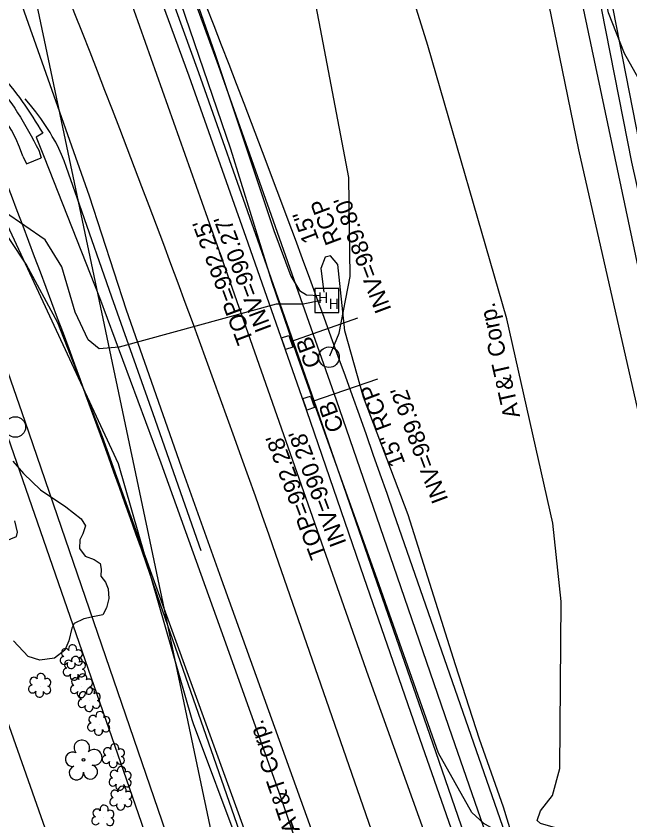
# Model space of a CAD drawing. Extents: x 1614427 to 1617186, y 896524 to 905462.
# Drawn here: x 1616176 to 1616323.1, y 903837.6 to 904030.2 of the extents above; entities that cross this region are included whole.
import ezdxf

# ---------------------------------------------------------------- set-up
doc = ezdxf.new("R2010")
doc.units = 0
for name, color, linetype in [('Exist Horizontal Alignment', 7, 'Continuous'), ('Exist Other Culture Fence Line', 7, 'Continuous'), ('Exist Right of Way Line', 7, 'Continuous'), ('Exist Roads Curbs', 7, 'Continuous'), ('Exist Roads EOP', 7, 'Continuous'), ('Exist Roads EOP Other', 7, 'Continuous'), ('Exist Roads EOT', 7, 'Continuous'), ('Exist Structure Minor Catch Basin', 7, 'Continuous'), ('Exist Structure Minor Catch Basin Text', 7, 'Continuous'), ('Exist Structure Minor Catch Basin Top Elevation', 7, 'Continuous'), ('Exist Structure Minor Pipes RCP 15 Inch', 7, 'Continuous'), ('Exist Structure Minor Pipes RCP 15 Inch Invert', 7, 'Continuous'), ('Exist Structure Minor Pipes RCP 15 Inch Text', 7, 'Continuous'), ('Exist Utilities Gas UG Line SUE LOS B', 7, 'Continuous'), ('Exist Utilities Other Pole CELL', 7, 'Continuous'), ('Exist Utilities Power UG Cable SUE LOS B', 7, 'Continuous'), ('Exist Utilities Power UG Cable SUE LOS D', 7, 'Continuous'), ('Exist Utilities Telephone Hand Hole CELL', 7, 'Continuous'), ('Exist Utilities Telephone UG Cable SUE LOS B', 7, 'Continuous'), ('Exist Utilities Telephone UG Cable SUE LOS B Text', 7, 'Continuous'), ('Exist Utilities Telephone UG FO SUE LOS B', 7, 'Continuous'), ('Exist Utilities Telephone UG FO SUE LOS B Text', 7, 'Continuous'), ('Exist Utilities Telephone UG FO SUE LOS D', 7, 'Continuous'), ('Exist Utilities TV UG Cable SUE LOS D', 7, 'Continuous'), ('Exist Utilities TV UG FO Cable SUE LOS D', 7, 'Continuous'), ('Exist Utilities Water UG Line SUE LOS B', 7, 'Continuous'), ('Exist Vegetation Hedge Row', 7, 'Continuous'), ('Exist Vegetation Shrub CELL', 7, 'Continuous'), ('Exist Vegetation Tree CELL', 7, 'Continuous'), ('Exist Vegetation Woods Line', 7, 'Continuous')]:
    doc.layers.add(name, color=color, linetype=linetype)

msp = doc.modelspace()

# ---------------------------------------------------------------- linework, layer by layer
at = {"layer": 'Exist Horizontal Alignment'}
msp.add_line((1616576.74, 902927.89), (1616238.24, 903901.21), dxfattribs=at)
msp.add_arc((1612992.37, 902768.76), 3437.75, 19.23333, 21.86667, dxfattribs=at)
at = {"layer": 'Exist Other Culture Fence Line'}
msp.add_lwpolyline([(1616211.35, 903767.58), (1616195.22, 903813.36), (1616186.56, 903825.42), (1616168.75, 903875.81), (1616153.63, 903916.5), (1616129.58, 903932.3), (1616098.05, 903952.43), (1616082.04, 903962.19), (1616045.01, 903949.52), (1616000.86, 903933.41), (1615934.86, 903910.4), (1615905.89, 903899.71)], dxfattribs=at)
at = {"layer": 'Exist Right of Way Line'}
for p, q in [((1616010.65, 905462.23), (1616993.32, 900797.76)), ((1615887.44, 905426.15), (1616864.55, 900788.06)), ((1616548.32, 902918.27), (1616209.91, 903891.34))]:
    msp.add_line(p, q, dxfattribs=at)
msp.add_lwpolyline([(1616348.8, 903674.62), (1616266.57, 903911.08), (1616266.56, 903911.09)], dxfattribs=at)
for radius, start, end in [(3467.75, 19.23333, 21.86667), (3407.75, 19.23358, 21.34613)]:
    msp.add_arc((1612992.37, 902768.76), radius, start, end, dxfattribs=at)
at = {"layer": 'Exist Roads Curbs'}
msp.add_line((1616181.42, 903998.08), (1616182.01, 903996.25), dxfattribs=at)
msp.add_lwpolyline([(1616117.86, 904294.32), (1616132.6, 904254.66), (1616147.03, 904215.59), (1616161.55, 904176.09), (1616175.82, 904137.25), (1616190.47, 904097.09), (1616204.98, 904057.33), (1616219.73, 904016.73), (1616233.88, 903976.63), (1616247.93, 903936.53), (1616261.75, 903896.6), (1616275.82, 903856.12), (1616289.5, 903816.57), (1616303.58, 903775.98), (1616318, 903734.48)], dxfattribs=at)
msp.add_spline([(1616134.69, 904023.46), (1616139.29, 904024.31), (1616146.51, 904024.55), (1616150.66, 904023.89), (1616157.04, 904022.42), (1616170, 904014.96), (1616181.42, 903998.08)], degree=3, dxfattribs=at)
at = {"layer": 'Exist Roads EOP'}
for points in [[(1616115.61, 904293.45), (1616130.22, 904253.88), (1616144.71, 904214.78), (1616159.36, 904175.17), (1616173.54, 904136.33), (1616188.19, 904096.22), (1616202.56, 904056.51), (1616217.36, 904015.9), (1616231.52, 903975.89), (1616245.62, 903935.7), (1616259.38, 903895.73), (1616273.35, 903855.36), (1616287.12, 903815.79), (1616301.21, 903775.08), (1616315.66, 903733.58)], [(1616115.61, 904293.45), (1616130.22, 904253.88), (1616144.71, 904214.78), (1616159.36, 904175.17), (1616173.54, 904136.33), (1616188.19, 904096.22), (1616202.56, 904056.51), (1616217.36, 904015.9), (1616231.52, 903975.89), (1616245.62, 903935.7), (1616259.38, 903895.73), (1616273.35, 903855.36), (1616287.12, 903815.79)], [(1616182.37, 904002.15), (1616180.78, 904001.18), (1616182.71, 903996.46), (1616196.01, 903962.82), (1616210.69, 903923.18), (1616225.09, 903883.2), (1616239.3, 903843.39), (1616253.05, 903803.36), (1616266.79, 903762.41), (1616281.33, 903720.95)]]:
    msp.add_lwpolyline(points, dxfattribs=at)
msp.add_spline([(1616134.32, 904025.99), (1616139, 904026.81), (1616146.76, 904026.96), (1616150.97, 904026.42), (1616157.68, 904024.84), (1616171.63, 904016.64), (1616182.37, 904002.15)], degree=3, dxfattribs=at)
at = {"layer": 'Exist Roads EOP Other'}
for points in [[(1616122.43, 904296.46), (1616137.34, 904256.3), (1616151.63, 904217.58), (1616166.45, 904177.4), (1616180.52, 904139.04), (1616195.16, 904098.73), (1616209.58, 904059.11), (1616224.45, 904018.46), (1616238.58, 903978.47), (1616252.68, 903938.24), (1616266.45, 903898.41), (1616280.47, 903857.78), (1616294.14, 903818.38), (1616308.3, 903777.63), (1616322.66, 903736.35)], [(1616177.61, 903996.7), (1616178.44, 903994.84), (1616181.96, 903996.23)]]:
    msp.add_lwpolyline(points, dxfattribs=at)
msp.add_ellipse((1616144.89, 903985.92), major_axis=(8.54, 33.37), ratio=0.999906, start_param=5.280969, end_param=6.32168, dxfattribs=at)
at = {"layer": 'Exist Roads EOT'}
msp.add_lwpolyline([(1616220.38, 903902.1), (1616208.82, 903934.88), (1616198.96, 903962.91), (1616191.16, 903985.11), (1616188.04, 903993.96), (1616187.51, 903995.51), (1616186.9, 903997.04), (1616186.23, 903998.53), (1616185.48, 903999.99), (1616184.66, 904001.41), (1616184.11, 904002.3), (1616183.05, 904004.02), (1616181.92, 904005.69), (1616180.72, 904007.32), (1616179.46, 904008.9), (1616178.14, 904010.43), (1616178.13, 904010.44)], dxfattribs=at)
at = {"layer": 'Exist Structure Minor Catch Basin'}
for points in [[(1616242.34, 903950.91), (1616240.54, 903950.31), (1616239.57, 903953.15), (1616241.39, 903953.73), (1616242.34, 903950.91)], [(1616247.49, 903936.4), (1616245.71, 903935.79), (1616244.74, 903938.57), (1616246.55, 903939.19), (1616247.49, 903936.4)]]:
    msp.add_lwpolyline(points, dxfattribs=at)
at = {"layer": 'Exist Structure Minor Pipes RCP 15 Inch'}
for p, q in [((1616241.86, 903952.26), (1616257.87, 903957.95)), ((1616241.86, 903952.26), (1616257.87, 903957.95)), ((1616262.61, 903943.26), (1616247.04, 903937.86)), ((1616262.61, 903943.26), (1616247.04, 903937.86))]:
    msp.add_line(p, q, dxfattribs=at)
at = {"layer": 'Exist Utilities Gas UG Line SUE LOS B'}
msp.add_lwpolyline([(1616229.48, 903831.39), (1616218.51, 903860.65), (1616218.15, 903861.58), (1616200.49, 903922.94), (1616158.51, 904013.15), (1616156.79, 904018.63), (1616125.02, 904117.19), (1616112.76, 904150.51)], dxfattribs=at)
at = {"layer": 'Exist Utilities Other Pole CELL'}
for centre in [(1616250.99, 903948.48), (1616175.8, 903931.77)]:
    msp.add_circle(centre, 2.46, dxfattribs=at)
at = {"layer": 'Exist Utilities Power UG Cable SUE LOS B'}
msp.add_lwpolyline([(1616251.18, 903948.78), (1616253.44, 903954.26), (1616256.05, 903967.83), (1616255.72, 903991.57), (1616246.33, 904041.11), (1616238.14, 904073.94), (1616217.33, 904136.89), (1616206.18, 904181.46), (1616196.65, 904215.76), (1616195.81, 904229.77), (1616189.23, 904257.04), (1616182.09, 904267.79), (1616161.47, 904291.96), (1616139.96, 904327.82), (1616127.72, 904364.11), (1616117.11, 904392.88), (1616109.92, 904408.61)], dxfattribs=at)
at = {"layer": 'Exist Utilities Power UG Cable SUE LOS D'}
msp.add_lwpolyline([(1616236.67, 903748.63), (1616173.38, 903931.36), (1616078.95, 904203.95), (1616024.11, 904362.27)], dxfattribs=at)
at = {"layer": 'Exist Utilities Telephone Hand Hole CELL'}
for p, q in [((1616247.59, 903964.96), (1616247.59, 903959.24)), ((1616253.32, 903964.96), (1616247.59, 903964.96)), ((1616253.32, 903959.24), (1616253.32, 903964.96)), ((1616250.46, 903962.1), (1616250.46, 903962.1)), ((1616247.59, 903959.24), (1616253.32, 903959.24))]:
    msp.add_line(p, q, dxfattribs=at)
at = {"layer": 'Exist Utilities Telephone UG Cable SUE LOS B'}
msp.add_lwpolyline([(1616264.73, 903785.56), (1616225.23, 903895.34), (1616215.6, 903922.1), (1616202.44, 903959.77), (1616193.59, 903987.06), (1616171.78, 904048.65), (1616147.44, 904117.95), (1616126.43, 904148.49), (1616103.05, 904238.24), (1616092.8, 904266.31), (1616073.76, 904321.1), (1616067.14, 904333.96), (1616066.19, 904334.49), (1616064.27, 904334.96), (1616057.18, 904332.89), (1616048.96, 904331.57)], dxfattribs=at)
at = {"layer": 'Exist Utilities Telephone UG FO SUE LOS B'}
for points in [[(1616305.86, 903835.58), (1616301.71, 903836.75), (1616300.93, 903837.51), (1616301.7, 903839.81), (1616304.58, 903843.5), (1616306.34, 903849.92), (1616306.68, 903889.95), (1616304.63, 903908.72), (1616293.63, 903957.65), (1616274.72, 904023.16), (1616260.11, 904069.82), (1616245.31, 904104.27), (1616231.41, 904145.88), (1616215.41, 904195.22), (1616204.68, 904240.22), (1616199.33, 904261.21), (1616183.55, 904304.43), (1616162.6, 904355.73), (1616148.58, 904401.99), (1616136.38, 904433.35), (1616120.49, 904476.41), (1616105.61, 904520.44), (1616089.41, 904571.33)], [(1616227.47, 903998.34), (1616211.12, 904046.11), (1616197.17, 904083.61), (1616180.84, 904129.23), (1616169.23, 904161.39), (1616162.49, 904178.57), (1616139.6, 904240.02), (1616090.77, 904372.44), (1616071.57, 904435.61), (1616056.71, 904499.76), (1616046.9, 904559.71)], [(1616174.04, 904166.31), (1616172.79, 904159.75), (1616179.29, 904147.79), (1616189.78, 904114.21), (1616200.72, 904084.94), (1616209.79, 904060.82), (1616223.62, 904021.24), (1616237.73, 903978.87), (1616241.81, 903967.87), (1616243.9, 903964.46), (1616245.56, 903963.47), (1616248.71, 903963.24)], [(1616249.11, 903962.1), (1616244.79, 903961.17), (1616238.35, 903961.16), (1616200.69, 903950.89), (1616195.93, 903950.49), (1616193.23, 903952.67), (1616190.15, 903959.25), (1616186.96, 903970.12), (1616182.94, 903976.59), (1616168.24, 903986.65), (1616161.85, 903994.6), (1616153.95, 904004.6), (1616148.06, 904010.09), (1616140.82, 904013.46), (1616124.88, 904014.78), (1616105.51, 904016.53), (1616064.53, 904012.24), (1616026.51, 904012.8), (1615984.81, 904011.98), (1615950.8, 904014.23), (1615922.36, 904016.58), (1615897.75, 904017.11), (1615884.16, 904015.33), (1615877.39, 904015.58)], [(1616231.95, 903831.99), (1616208.49, 903896.38), (1616196.66, 903929.39), (1616185.98, 903956.69), (1616178.38, 903970.82), (1616170.63, 903982.39), (1616159.03, 903993.51), (1616152.27, 904000.63), (1616146.16, 904003.93), (1616135.11, 904008.46), (1616113.93, 904008.67), (1616072.1, 904003.93), (1616027.82, 904003.5), (1615985.23, 904002.2), (1615950.55, 904003.04), (1615906.43, 904005.88), (1615898.01, 904002.34)], [(1616305.43, 903834.95), (1616296.33, 903833.77), (1616291.87, 903834.62), (1616288.13, 903836.73), (1616285.25, 903839.39), (1616277.28, 903853.64), (1616262.51, 903895.33), (1616243.28, 903949.17), (1616237.33, 903966.37), (1616227.47, 903998.34)], [(1616287.08, 903856.98), (1616281.28, 903874.75), (1616269.99, 903910.7), (1616259.25, 903938.88), (1616254.76, 903954.77), (1616253.07, 903970.72), (1616251.35, 903972.79), (1616250.05, 903972.47), (1616249.02, 903969.73), (1616249.73, 903964.06)], [(1616301.65, 903812.03), (1616292.8, 903840.69), (1616287.08, 903856.98)]]:
    msp.add_lwpolyline(points, dxfattribs=at)
at = {"layer": 'Exist Utilities Telephone UG FO SUE LOS D'}
msp.add_lwpolyline([(1616412.38, 903583.74), (1616374.62, 903777.9), (1616326.11, 903996.08), (1616269.81, 904283.52), (1616224.71, 904447.92), (1616220.83, 904470.3)], dxfattribs=at)
at = {"layer": 'Exist Utilities TV UG Cable SUE LOS D'}
msp.add_lwpolyline([(1616295.86, 903492.41), (1616273.81, 903595.89), (1616240.99, 903749.89), (1616178.16, 903933.06), (1616083.67, 904205.09), (1616028.66, 904363.47)], dxfattribs=at)
at = {"layer": 'Exist Utilities TV UG FO Cable SUE LOS D'}
msp.add_lwpolyline([(1616615.13, 902920.57), (1616559.6, 903084.29), (1616508.29, 903236.97), (1616433.95, 903449.2), (1616409.28, 903583.28), (1616372.35, 903777.82), (1616323.57, 903995.2), (1616266.96, 904282.87), (1616220.39, 904446.95), (1616216.24, 904469.3), (1616198.7, 904563.75), (1616189.79, 904725.95), (1616160.9, 904944.94), (1616137.72, 905120.69)], dxfattribs=at)
at = {"layer": 'Exist Utilities Water UG Line SUE LOS B'}
msp.add_lwpolyline([(1616526.94, 903118.95), (1616504.59, 903181.23), (1616480.02, 903252.46), (1616446.17, 903345), (1616411.28, 903445.17), (1616385.62, 903515.15), (1616350.02, 903616.87), (1616323.73, 903691.37), (1616291.21, 903786.26), (1616260.45, 903872.07), (1616224.66, 903974.02), (1616192.08, 904066.13), (1616173.94, 904118.11), (1616130.42, 904237.78), (1616097.26, 904331.65), (1616083.48, 904374.45), (1616069.85, 904420.53), (1616059.14, 904458.49), (1616050.85, 904496.39), (1616045.84, 904527.76), (1616030.28, 904669.9)], dxfattribs=at)
at = {"layer": 'Exist Vegetation Hedge Row'}
for points in [[(1616358.61, 903855.18), (1616347.94, 903857.23), (1616338.59, 903879.82), (1616325.43, 903934.2), (1616310.92, 903998.19), (1616300.46, 904048.92), (1616299.41, 904076.85), (1616293.79, 904094.09), (1616289.23, 904099.45), (1616283.51, 904102.81), (1616273.57, 904103.44), (1616270.33, 904105.91), (1616268.99, 904109.41), (1616269.89, 904113.78), (1616274.57, 904118.52), (1616280.14, 904127.79), (1616280.93, 904138.82), (1616278.97, 904162.54), (1616274.72, 904185.17), (1616262.08, 904240.76), (1616253.29, 904278.87)], [(1616175.22, 903923.56), (1616177.74, 903920.65), (1616181.81, 903916.73), (1616187.91, 903912.61), (1616191.57, 903909.72), (1616192.58, 903908.06), (1616191.97, 903906.19), (1616191.26, 903904.72), (1616191.19, 903902.61), (1616192.51, 903900.8), (1616194.66, 903900.03), (1616196.17, 903899.02), (1616196.34, 903897.7), (1616196.32, 903896.05), (1616197.4, 903894.56), (1616198.07, 903892.95), (1616198.2, 903890.7), (1616197.62, 903888.47), (1616196.77, 903886.75), (1616194.75, 903886.38), (1616192.22, 903885.82), (1616189.91, 903884.65), (1616189.34, 903883.59), (1616188.66, 903880.49), (1616187.64, 903878.32), (1616185.16, 903876.37), (1616181.69, 903875.89), (1616178.86, 903876.75), (1616175.33, 903880.56)], [(1616173.36, 903904.42), (1616176.09, 903905.55), (1616176.32, 903906.53), (1616175.65, 903909.29)]]:
    msp.add_lwpolyline(points, dxfattribs=at)
at = {"layer": 'Exist Vegetation Shrub CELL'}
for p, q in [((1616189.3, 903876.55), (1616189.3, 903876.55)), ((1616190.01, 903873.77), (1616190.01, 903873.77)), ((1616181.72, 903869.69), (1616181.72, 903869.69)), ((1616191.74, 903869.57), (1616191.74, 903869.57)), ((1616193.58, 903866.24), (1616193.58, 903866.24)), ((1616195.87, 903860.56), (1616195.87, 903860.56)), ((1616199.37, 903852.83), (1616199.37, 903852.83)), ((1616201, 903847.4), (1616201, 903847.4)), ((1616201.17, 903842.64), (1616201.17, 903842.64)), ((1616196.86, 903838.12), (1616196.86, 903838.12))]:
    msp.add_line(p, q, dxfattribs=at)
for centre, radius, start, end in [((1616189.53, 903878.59), 0.99, 334.8391, 200.4717), ((1616187.81, 903877.68), 0.968, 35.8908, 245.4216), ((1616190.97, 903877.42), 0.929, 284.4567, 126.0861), ((1616187.5, 903875.84), 0.955, 95.1099, 327.9534), ((1616188.53, 903874.89), 0.968, 35.8908, 245.4216), ((1616190.24, 903875.81), 0.99, 334.8391, 200.4717), ((1616190.93, 903875.62), 0.937, 204.9913, 73.4601), ((1616191.68, 903874.64), 0.929, 284.4567, 126.0861), ((1616188.21, 903873.06), 0.955, 95.1099, 327.9534), ((1616189.17, 903874.86), 0.984, 151.2797, 21.387), ((1616191.65, 903872.84), 0.937, 204.9913, 73.4601), ((1616180.24, 903870.82), 0.968, 35.8908, 245.4216), ((1616181.95, 903871.73), 0.99, 334.8391, 200.4717), ((1616189.88, 903872.08), 0.984, 151.2797, 21.387), ((1616191.97, 903871.61), 0.99, 334.8391, 200.4717), ((1616179.92, 903868.99), 0.955, 95.1099, 327.9534), ((1616183.4, 903870.56), 0.929, 284.4567, 126.0861), ((1616189.94, 903868.87), 0.955, 95.1099, 327.9534), ((1616190.26, 903870.7), 0.968, 35.8908, 245.4216), ((1616193.41, 903870.44), 0.929, 284.4567, 126.0861), ((1616181.6, 903868.01), 0.984, 151.2797, 21.387), ((1616183.36, 903868.76), 0.937, 204.9913, 73.4601), ((1616191.61, 903867.89), 0.984, 151.2797, 21.387), ((1616192.1, 903867.36), 0.968, 35.8908, 245.4216), ((1616193.38, 903868.64), 0.937, 204.9913, 73.4601), ((1616193.81, 903868.28), 0.99, 334.8391, 200.4717), ((1616195.25, 903867.11), 0.929, 284.4567, 126.0861), ((1616191.78, 903865.53), 0.955, 95.1099, 327.9534), ((1616195.22, 903865.31), 0.937, 204.9913, 73.4601), ((1616193.45, 903864.55), 0.984, 151.2797, 21.387), ((1616194.39, 903861.69), 0.968, 35.8908, 245.4216), ((1616196.1, 903862.6), 0.99, 334.8391, 200.4717), ((1616197.54, 903861.43), 0.929, 284.4567, 126.0861), ((1616194.07, 903859.86), 0.955, 95.1099, 327.9534), ((1616197.51, 903859.63), 0.937, 204.9913, 73.4601), ((1616195.74, 903858.88), 0.984, 151.2797, 21.387), ((1616197.89, 903853.95), 0.968, 35.8908, 245.4216), ((1616199.6, 903854.87), 0.99, 334.8391, 200.4717), ((1616201.04, 903853.69), 0.929, 284.4567, 126.0861), ((1616197.57, 903852.12), 0.955, 95.1099, 327.9534), ((1616201.01, 903851.9), 0.937, 204.9913, 73.4601), ((1616199.24, 903851.14), 0.984, 151.2797, 21.387), ((1616199.51, 903848.53), 0.968, 35.8908, 245.4216), ((1616201.23, 903849.44), 0.99, 334.8391, 200.4717), ((1616202.67, 903848.27), 0.929, 284.4567, 126.0861), ((1616199.2, 903846.69), 0.955, 95.1099, 327.9534), ((1616202.63, 903846.47), 0.937, 204.9913, 73.4601), ((1616199.68, 903843.77), 0.968, 35.8908, 245.4216), ((1616200.87, 903845.71), 0.984, 151.2797, 21.387), ((1616201.39, 903844.68), 0.99, 334.8391, 200.4717), ((1616199.37, 903841.93), 0.955, 95.1099, 327.9534), ((1616202.84, 903843.51), 0.929, 284.4567, 126.0861), ((1616197.09, 903840.16), 0.99, 334.8391, 200.4717), ((1616201.04, 903840.96), 0.984, 151.2797, 21.387), ((1616202.8, 903841.71), 0.937, 204.9913, 73.4601), ((1616195.38, 903839.25), 0.968, 35.8908, 245.4216), ((1616198.53, 903838.99), 0.929, 284.4567, 126.0861), ((1616195.06, 903837.42), 0.955, 95.1099, 327.9534), ((1616198.5, 903837.19), 0.937, 204.9913, 73.4601)]:
    msp.add_arc(centre, radius, start, end, dxfattribs=at)
at = {"layer": 'Exist Vegetation Tree CELL'}
msp.add_line((1616192.13, 903852), (1616192.13, 903852), dxfattribs=at)
msp.add_circle((1616192.13, 903852), 0.326, dxfattribs=at)
for centre, radius, start, end in [((1616191.74, 903854.88), 1.86, 330.1651, 219.7134), ((1616194.68, 903852.59), 1.9, 257.1011, 134.1999), ((1616189.52, 903852.16), 1.73, 62.6636, 279.3457), ((1616193.8, 903849.1), 1.7, 181.2822, 74.56), ((1616190.42, 903848.88), 1.69, 111.5671, 6.231)]:
    msp.add_arc(centre, radius, start, end, dxfattribs=at)
at = {"layer": 'Exist Vegetation Woods Line'}
msp.add_lwpolyline([(1616365.59, 903820.6), (1616353.15, 903884.59), (1616347.73, 903925.27), (1616338.73, 903963.54), (1616335.36, 903990.43), (1616333.66, 903998.74), (1616328.38, 904009.6), (1616321.8, 904021.23), (1616318.01, 904031.04), (1616304.54, 904095.81), (1616295.76, 904137.81), (1616284.29, 904196.22), (1616273.61, 904253.55), (1616273.63, 904261.89), (1616276.22, 904274.47), (1616277.23, 904281.08), (1616276.85, 904288.34)], dxfattribs=at)

# ---------------------------------------------------------------- texts
at = {"layer": 'Exist Structure Minor Catch Basin Text'}
for p in [(1616249.23, 903946.85), (1616254.66, 903931.41)]:
    msp.add_text('CB', height=4, rotation=110.55, dxfattribs=at).set_placement(p)
at = {"layer": 'Exist Structure Minor Catch Basin Top Elevation'}
for s, p in [("TOP=992.25'", (1616232.93, 903952.43)), ("TOP=992.28'", (1616250.5, 903901))]:
    msp.add_text(s, height=4, rotation=110.55, dxfattribs=at).set_placement(p)
at = {"layer": 'Exist Structure Minor Pipes RCP 15 Inch Invert'}
for s, p in [("INV=989.80'", (1616266.02, 903959.95)), ("INV=990.27'", (1616237.3, 903955.4)), ("INV=989.92'", (1616279.63, 903914.38)), ("INV=990.28'", (1616255.22, 903903.97))]:
    msp.add_text(s, height=4, rotation=110.55, dxfattribs=at).set_placement(p)
at = {"layer": 'Exist Structure Minor Pipes RCP 15 Inch Text'}
for s, p in [('RCP', (1616254.11, 903976.32)), ('15" ', (1616248.64, 903976.66)), ('15" RCP', (1616269.33, 903923.1))]:
    msp.add_text(s, height=4, rotation=110.55, dxfattribs=at).set_placement(p)
at = {"layer": 'Exist Utilities Telephone Hand Hole CELL'}
for p in [(1616248.37, 903961.51), (1616250.94, 903960.04)]:
    msp.add_text('H', height=2.5, dxfattribs=at).set_placement(p)
at = {"layer": 'Exist Utilities Telephone UG Cable SUE LOS B Text'}
msp.add_text('AT&T Corp.', height=4, rotation=108.5895, dxfattribs=at).set_placement((1616244.03, 903835.18))
at = {"layer": 'Exist Utilities Telephone UG FO SUE LOS B Text'}
msp.add_text('AT&T Corp.', height=4, rotation=102.6716, dxfattribs=at).set_placement((1616296.83, 903934.3))

doc.saveas('drawing.dxf')
